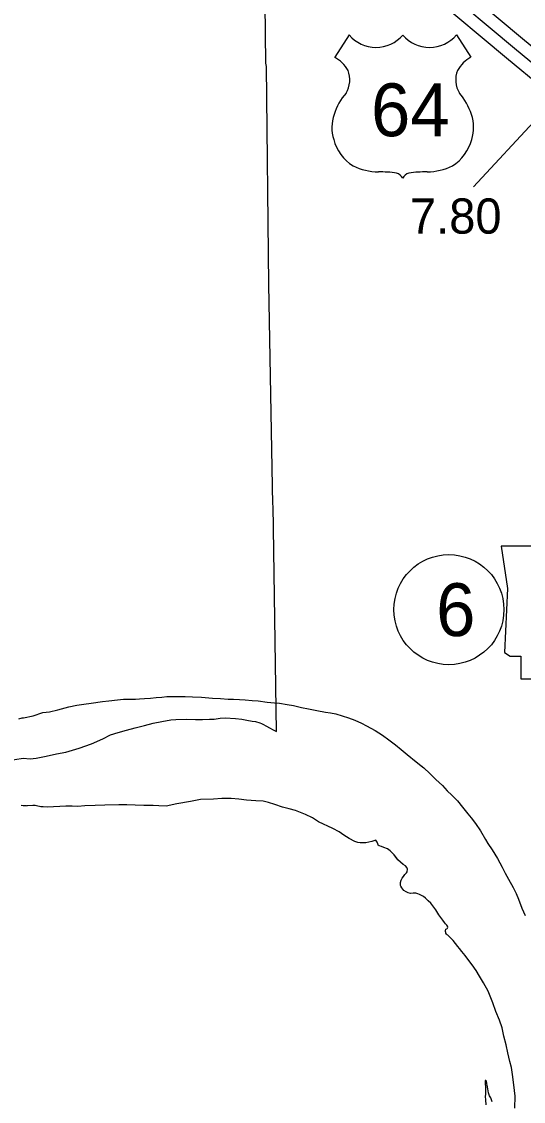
# Model space of a CAD drawing. Extents: x -83719 to 153526, y -11835 to 11446.
# Drawn here: x -664 to -463.2, y 426.5 to 857.9 of the extents above; entities that cross this region are included whole.
import ezdxf

# ---------------------------------------------------------------- set-up
doc = ezdxf.new("R2010")
doc.units = 0
for name, color, linetype in [('Level 15', 7, 'Continuous'), ('Level 2', 7, 'Continuous'), ('Level 21', 7, 'Continuous'), ('Level 22', 7, 'Continuous'), ('Level 25', 7, 'Continuous'), ('Level 27', 7, 'Continuous'), ('Level 59', 7, 'Continuous'), ('Level 9', 7, 'Continuous')]:
    doc.layers.add(name, color=color, linetype=linetype)

msp = doc.modelspace()

# ---------------------------------------------------------------- linework, layer by layer
at = {"layer": 'Level 15'}
for points in [[(-493.52, 876.34), (-463.58, 851.14), (-449.04, 839.24)], [(-499.92, 868.65), (-469.97, 843.44), (-455.41, 831.52)]]:
    msp.add_lwpolyline(points, dxfattribs=at)
at = {"layer": 'Level 2'}
for points in [[(-561.97, 574.36), (-563.34, 664.48), (-563.45, 665.01), (-565.03, 752.86), (-565.98, 840.04), (-566.19, 841.27), (-567.16, 924.54)], [(-561.97, 574.36), (-563.34, 664.48), (-563.45, 665.01), (-565.03, 752.86), (-565.98, 840.04), (-566.19, 841.27), (-567.16, 924.3)], [(-663.29, 563.62), (-660.58, 563.4), (-658.18, 563.62), (-654.16, 564.51), (-649.93, 565.34), (-646.24, 566), (-640.96, 567.71), (-635.97, 569.35), (-631.39, 571.41), (-628.34, 572.97), (-625.28, 573.93), (-621.99, 574.79), (-618.57, 575.71), (-614.84, 576.67), (-611.29, 577.6), (-607.9, 578.36), (-604.24, 578.91), (-602.21, 579.16), (-598.01, 579.19), (-594.38, 579.08), (-591.55, 579.14), (-588.79, 579.19), (-586.92, 579.3), (-584.49, 579.65), (-582.49, 579.73), (-578.43, 579.56), (-575.86, 579.24), (-573.8, 578.89), (-571.7, 578.5), (-570.43, 578.25), (-568.69, 577.82), (-568.02, 577.56), (-565.48, 576.14), (-565.28, 576.01), (-564.48, 575.58), (-563.54, 575.12), (-561.97, 574.36)], [(-663.29, 563.62), (-660.58, 563.4), (-658.18, 563.62), (-654.16, 564.51), (-649.93, 565.34), (-646.24, 566), (-640.96, 567.71), (-635.97, 569.35), (-631.39, 571.41), (-628.34, 572.97), (-625.28, 573.93), (-621.99, 574.79), (-618.57, 575.71), (-614.84, 576.67), (-611.29, 577.6), (-607.9, 578.36), (-604.24, 578.91), (-602.21, 579.16), (-598.01, 579.19), (-594.38, 579.08), (-591.55, 579.14), (-588.79, 579.19), (-586.92, 579.3), (-584.49, 579.65), (-582.49, 579.73), (-578.43, 579.56), (-575.86, 579.24), (-573.8, 578.89), (-571.7, 578.5), (-570.43, 578.25), (-568.69, 577.82), (-568.02, 577.56), (-565.48, 576.14), (-565.28, 576.01), (-564.48, 575.58), (-563.54, 575.12), (-561.97, 574.36)], [(-670.01, 562.64), (-663.29, 563.62)], [(-670.01, 562.64), (-663.29, 563.62)]]:
    msp.add_lwpolyline(points, dxfattribs=at)
at = {"layer": 'Level 21'}
msp.add_lwpolyline([(-472.14, 648.4), (-469.6, 631.48), (-470.73, 605.82), (-468.47, 604.41), (-464.25, 604.41), (-464.25, 595.39), (-428.72, 595.39), (-427.03, 599.06), (-427.59, 604.98), (-426.74, 611.75), (-423.64, 617.1), (-421.67, 621.05), (-418.85, 625.28), (-417.16, 629.79), (-415.75, 633.46), (-413.21, 636.56), (-412.65, 638.53), (-413.77, 639.94), (-422.51, 639.94), (-420.54, 643.89), (-420.26, 646.43), (-421.43, 648.38)], close=True, dxfattribs=at)
at = {"layer": 'Level 22'}
for p, q in [((-532.93, 852.62), (-538.7, 843.7)), ((-490.04, 852.62), (-484.27, 843.7))]:
    msp.add_line(p, q, dxfattribs=at)
for centre, radius, start, end in [((-522.19, 861.66), 14.04, 220.075, 319.6701), ((-500.78, 861.66), 14.04, 220.3299, 319.925), ((-546.24, 830.75), 14.99, 30.7809, 59.9883), ((-476.73, 830.75), 14.99, 120.0117, 149.2191), ((-542.94, 834.7), 10.28, 328.8105, 21.2108), ((-480.03, 834.7), 10.28, 158.7892, 211.1895), ((-516.07, 813.64), 23.97, 138.9565, 162.6913), ((-506.9, 813.64), 23.97, 17.3087, 41.0435), ((-523.99, 815.6), 15.84, 160.9576, 197.3819), ((-498.98, 815.6), 15.84, 342.6181, 19.0424), ((-521.41, 815.65), 18.33, 195.1074, 237.1312), ((-501.56, 815.65), 18.33, 302.8688, 344.8926), ((-521.07, 821.42), 23.53, 244.0771, 269.5779), ((-501.9, 821.42), 23.53, 270.4221, 295.9229), ((-520.52, 754.78), 43.11, 81.1942, 90.9539), ((-515.13, 793.43), 4.13, 28.0342, 72.9864), ((-507.84, 793.43), 4.13, 107.0136, 151.9658), ((-502.45, 754.78), 43.11, 89.0461, 98.8058)]:
    msp.add_arc(centre, radius, start, end, dxfattribs=at)
at = {"layer": 'Level 25'}
msp.add_line((-483.23, 791.88), (-457.51, 819.59), dxfattribs=at)
at = {"layer": 'Level 27'}
msp.add_circle((-493.02, 622.99), 22, dxfattribs=at)
at = {"layer": 'Level 59'}
msp.add_lwpolyline([(-496.72, 872.5), (-466.77, 847.29), (-452.23, 835.38)], dxfattribs=at)
at = {"layer": 'Level 9'}
for points in [[(-663.2, 579.74), (-659.33, 580.54), (-655.48, 581.87), (-652.78, 582.15), (-649.46, 582.98), (-645.04, 584.21), (-641.88, 584.83), (-639.05, 585.29), (-636.09, 585.61), (-631.6, 586.27), (-629, 586.52), (-625.61, 586.91), (-623.15, 587.2), (-618.45, 587.2), (-616.82, 587.31), (-614.79, 587.49), (-612.39, 587.67), (-610.06, 587.89), (-607.8, 588.07), (-605.83, 588.25), (-602.77, 588.27), (-600.61, 588.36), (-598.51, 588.34), (-595.54, 588.22), (-592.01, 587.98), (-587.65, 587.61), (-584.35, 587.43), (-581.32, 587.29), (-579.18, 587.2), (-576.79, 587.15), (-574.52, 587), (-571.72, 586.72), (-569.32, 586.5), (-565.72, 586.09), (-562.85, 585.78), (-560.82, 585.59), (-557.72, 585.11), (-555.15, 584.66), (-551.95, 583.92), (-549.15, 583.34), (-545.88, 582.69), (-542.45, 582.08), (-540.45, 581.79), (-538.31, 581.34), (-535.77, 580.62), (-533.17, 579.81), (-530.6, 578.89), (-528.03, 577.67), (-525.92, 576.62), (-522.58, 574.77), (-519.53, 572.79), (-516.99, 570.94), (-514.41, 568.92), (-512.17, 567.13), (-509.72, 565.17), (-506.07, 562.16), (-503.06, 559.74), (-500.67, 557.56), (-498.23, 555.2), (-495.61, 552.68), (-493.67, 550.66), (-491.85, 548.9), (-489.64, 546.58), (-487.52, 544.02), (-485.44, 541.47), (-484.13, 539.87), (-482.45, 537.51), (-480.43, 534.56), (-478.44, 531.16), (-477.4, 529.57), (-475.68, 527.04), (-473.59, 523.52), (-471.77, 520.12), (-470.55, 517.69), (-469.14, 515.27), (-467.31, 511.97), (-466.13, 509.61), (-465.25, 507.38), (-463.83, 503.78), (-462.47, 500.85)], [(-663.2, 579.74), (-659.33, 580.54), (-655.48, 581.87), (-652.78, 582.15), (-649.46, 582.98), (-645.04, 584.21), (-641.88, 584.83), (-639.05, 585.29), (-636.09, 585.61), (-631.6, 586.27), (-629, 586.52), (-625.61, 586.91), (-623.15, 587.2), (-618.45, 587.2), (-616.82, 587.31), (-614.79, 587.49), (-612.39, 587.67), (-610.06, 587.89), (-607.8, 588.07), (-605.83, 588.25), (-602.77, 588.27), (-600.61, 588.36), (-598.51, 588.34), (-595.54, 588.22), (-592.01, 587.98), (-587.65, 587.61), (-584.35, 587.43), (-581.32, 587.29), (-579.18, 587.2), (-576.79, 587.15), (-574.52, 587), (-571.72, 586.72), (-569.32, 586.5), (-565.72, 586.09), (-562.85, 585.78), (-560.82, 585.59), (-557.72, 585.11), (-555.15, 584.66), (-551.95, 583.92), (-549.15, 583.34), (-545.88, 582.69), (-542.45, 582.08), (-540.45, 581.79), (-538.31, 581.34), (-535.77, 580.62), (-533.17, 579.81), (-530.6, 578.89), (-528.03, 577.67), (-525.92, 576.62), (-522.58, 574.77), (-519.53, 572.79), (-516.99, 570.94), (-514.41, 568.92), (-512.17, 567.13), (-509.72, 565.17), (-506.07, 562.16), (-503.49, 560.09)], [(-665.06, 579.4), (-663.73, 579.71), (-663.2, 579.74)], [(-665.06, 579.4), (-663.73, 579.71), (-663.2, 579.74)], [(-664.1, 544.83), (-663.3, 544.8), (-662.6, 544.8), (-662.1, 544.76), (-661.74, 544.67)], [(-664.1, 544.83), (-663.3, 544.8), (-662.6, 544.8), (-662.1, 544.76), (-661.74, 544.67)], [(-530.62, 530.34), (-532.9, 531.56), (-535.07, 532.94), (-536.91, 534.17), (-539.45, 535.62), (-545.23, 538.28), (-547.54, 539.84), (-550.45, 541.12), (-554.42, 542.79), (-556.89, 543.44), (-559.63, 544.03), (-562.6, 545.08), (-565.14, 545.96), (-567.34, 546.44), (-570.27, 546.62), (-573.94, 546.9), (-577.1, 547.25), (-580.1, 547.56), (-583.8, 547.53), (-587.23, 547.31), (-592.39, 547.11), (-596.45, 546.38), (-601.83, 545.41), (-606.12, 544.51), (-609.06, 544.55), (-611.26, 544.74), (-615.02, 544.81), (-618.48, 544.89), (-621.91, 545.03), (-625.11, 544.98), (-630.71, 544.84), (-634.57, 544.75), (-638.66, 544.62), (-641.39, 544.4), (-643.69, 544.42), (-646.19, 544.5), (-648.59, 544.35), (-651.18, 544.23), (-653.71, 544.11), (-655.25, 544.2), (-656.25, 544.26), (-658.01, 544.65), (-658.45, 544.75), (-659.51, 544.77), (-661.74, 544.67)], [(-530.62, 530.34), (-532.9, 531.56), (-535.07, 532.94), (-536.91, 534.17), (-539.45, 535.62), (-545.23, 538.28), (-547.54, 539.84), (-550.45, 541.12), (-554.42, 542.79), (-556.89, 543.44), (-559.63, 544.03), (-562.6, 545.08), (-565.14, 545.96), (-567.34, 546.44), (-570.27, 546.62), (-573.94, 546.9), (-577.1, 547.25), (-580.1, 547.56), (-583.8, 547.53), (-587.23, 547.31), (-592.39, 547.11), (-596.45, 546.38), (-601.83, 545.41), (-606.12, 544.51), (-609.06, 544.55), (-611.26, 544.74), (-615.02, 544.81), (-618.48, 544.89), (-621.91, 545.03), (-625.11, 544.98), (-630.71, 544.84), (-634.57, 544.75), (-638.66, 544.62), (-641.39, 544.4), (-643.69, 544.42), (-646.19, 544.5), (-648.59, 544.35), (-651.18, 544.23), (-653.71, 544.11), (-655.25, 544.2), (-656.25, 544.26), (-658.01, 544.65), (-658.45, 544.75), (-659.51, 544.77), (-661.74, 544.67)], [(-466.59, 423.89), (-466.53, 428.63), (-467.06, 433.2), (-467.55, 437.24), (-468, 440.04), (-468.59, 442.47), (-469.45, 445.97), (-470.17, 449.08), (-471.02, 452.61), (-471.78, 455.91), (-472.84, 459.04), (-474.26, 462.4), (-475.45, 465.9), (-477.28, 470.53), (-479.2, 473.96), (-480.79, 476.55), (-482.17, 478.81), (-483.75, 481.07), (-485.4, 483.33), (-486.47, 484.76), (-487.82, 486.39), (-488.82, 487.68), (-489.43, 488.48), (-491.38, 490.77), (-492.45, 491.9), (-493.46, 492.93), (-493.69, 493.12), (-493.96, 493.39), (-494.23, 493.72), (-494.3, 494.06), (-494.4, 494.42), (-494.4, 494.79), (-494.21, 495.36), (-493.81, 495.46), (-493.54, 495.76), (-493.51, 496.1), (-493.52, 496.5), (-493.82, 496.96), (-494.36, 497.49), (-494.76, 497.99), (-495.46, 498.96), (-497.01, 501.12), (-498.19, 503.04), (-500.24, 505.74), (-501.28, 506.63), (-502.45, 507.79), (-503.22, 508.39), (-503.96, 508.81), (-504.76, 509.18), (-505.5, 509.47), (-506.2, 509.7), (-507.33, 509.73), (-508.36, 509.65), (-509.33, 509.85), (-510.17, 510.24), (-511.04, 510.84), (-511.81, 511.8), (-512.28, 512.53), (-512.35, 512.76), (-512.42, 513.16), (-512.42, 513.87), (-512.42, 513.97), (-512.06, 514.87), (-511.7, 515.67), (-511.24, 516.38), (-510.65, 517.18), (-509.99, 517.82), (-509.66, 518.23), (-509.63, 519.26), (-509.9, 520.03), (-510.44, 520.66), (-511.34, 521.22), (-513.42, 523.07), (-514.93, 525), (-515.64, 525.76), (-516.48, 526.59), (-517.65, 527.45), (-519.02, 528.01), (-519.98, 528.31), (-520.95, 528.6), (-521.35, 528.9), (-521.49, 529.46), (-521.7, 530.06), (-521.93, 530.56), (-522.3, 530.83), (-523.9, 530.38), (-526.29, 529.8), (-528.49, 529.78), (-529.39, 529.98), (-530.62, 530.34)], [(-513.56, 523.25), (-514.93, 525), (-515.64, 525.76), (-516.48, 526.59), (-517.65, 527.45), (-519.02, 528.01), (-519.98, 528.31), (-520.95, 528.6), (-521.35, 528.9), (-521.49, 529.46), (-521.7, 530.06), (-521.93, 530.56), (-522.3, 530.83), (-523.9, 530.38), (-526.29, 529.8), (-528.49, 529.78), (-529.39, 529.98), (-530.62, 530.34)], [(-475.75, 426.34), (-476.3, 427.97), (-476.75, 428.8), (-477.13, 429.9), (-477.48, 431.6), (-477.67, 432.96), (-477.84, 433.6), (-477.91, 434), (-477.92, 434.2), (-477.92, 434.26), (-477.99, 434.53), (-478.05, 434.59), (-478.22, 434.83), (-478.32, 434.89), (-478.49, 434.86), (-478.56, 434.82), (-478.55, 434.42), (-478.57, 433.49), (-478.42, 432.32), (-478.41, 431.05), (-478.39, 429.48), (-478.47, 428.54), (-478.45, 427.11), (-478.2, 425.21)]]:
    msp.add_lwpolyline(points, dxfattribs=at)

# ---------------------------------------------------------------- texts
at = {"layer": 'Level 22'}
msp.add_text('64', height=21.12, dxfattribs=at).set_placement((-524.17, 812.13))
at = {"layer": 'Level 25'}
msp.add_text('7.80', height=14.08, dxfattribs=at).set_placement((-508.61, 773.21))
at = {"layer": 'Level 27'}
msp.add_text('6', height=21.12, dxfattribs=at).set_placement((-498.13, 612.43))

doc.saveas('drawing.dxf')
